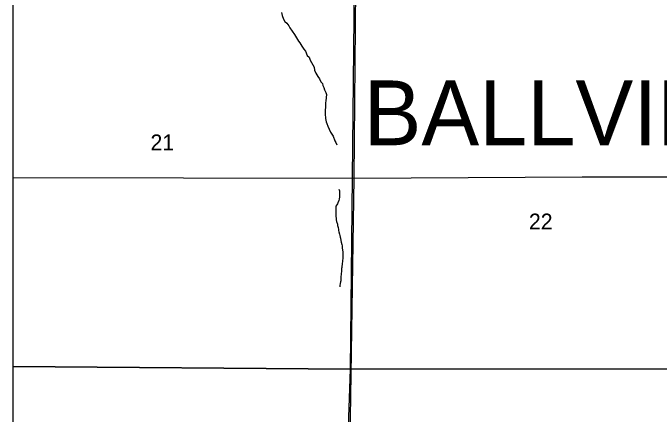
# Model space of a CAD drawing. Extents: x -8.5 to 18.7, y -20.3 to 7.
# Drawn here: x -8.459 to -5.057, y -7.025 to -4.913 of the extents above; entities that cross this region are included whole.
import ezdxf

# ---------------------------------------------------------------- set-up
doc = ezdxf.new("R2010")
doc.units = 0
for name, color, linetype in [('Default', 7, 'Continuous'), ('GM_X_Corporation', 7, 'Continuous'), ('GM_X_County_Road', 7, 'Continuous'), ('GM_X_Minor_River', 7, 'Continuous'), ('GM_X_Section', 7, 'Continuous'), ('GM_X_Section_Text', 7, 'Continuous'), ('GM_X_Township_Text', 7, 'Continuous'), ('SH_Cut_Line', 7, 'Continuous')]:
    doc.layers.add(name, color=color, linetype=linetype)

msp = doc.modelspace()

# ---------------------------------------------------------------- linework, layer by layer
at = {"layer": 'Default'}
for points in [[(-8.4587, -4.7633), (-8.4587, -6.7745), (-6.6812, -6.7894), (-6.6598, -4.7688)], [(-8.4587, -6.7745), (-8.4587, -8.687), (-6.7452, -8.6232), (-6.7444, -8.6126), (-6.6812, -6.7894)]]:
    msp.add_lwpolyline(points, close=True, dxfattribs=at)
at = {"layer": 'GM_X_Corporation'}
msp.add_lwpolyline([(-8.4587, 1.1732), (-8.4587, -10.6981)], dxfattribs=at)
at = {"layer": 'GM_X_County_Road'}
msp.add_line((-8.4587, -5.7791), (-6.6624, -5.7822), dxfattribs=at)
for points in [[(-6.6624, -5.7822), (-6.6535, -4.7817), (-6.634, -2.8913)], [(-6.8604, -10.6554), (-6.8095, -9.6404), (-6.7791, -9.1887), (-6.7402, -8.6177), (-6.6826, -7.1587), (-6.6624, -5.7822)], [(-6.6624, -5.7822), (-5.462, -5.7761), (-4.7817, -5.7756), (-4.6868, -5.7764), (-4.4626, -5.7723)]]:
    msp.add_lwpolyline(points, dxfattribs=at)
at = {"layer": 'GM_X_Minor_River'}
for points in [[(-7.044, -4.9105), (-7.0419, -4.9264), (-7.0345, -4.9462), (-7.0278, -4.9585), (-7.0172, -4.9677), (-7.0067, -4.9807), (-7.0015, -4.9906), (-6.9888, -5.0089), (-6.9768, -5.0258), (-6.9648, -5.0449), (-6.9544, -5.0609), (-6.9476, -5.0709), (-6.9379, -5.0884), (-6.9275, -5.1045), (-6.9185, -5.1144), (-6.9103, -5.1365), (-6.899, -5.1465), (-6.8931, -5.1625), (-6.8804, -5.1862), (-6.873, -5.1992), (-6.8708, -5.2136), (-6.8642, -5.2304), (-6.8537, -5.2472), (-6.844, -5.2602), (-6.838, -5.2754), (-6.8283, -5.2854), (-6.8261, -5.2953), (-6.8224, -5.306), (-6.818, -5.3181), (-6.8113, -5.3319), (-6.8083, -5.3433), (-6.8109, -5.3752), (-6.8126, -5.3865), (-6.8135, -5.4048), (-6.8153, -5.429), (-6.8154, -5.445), (-6.8126, -5.4685), (-6.8098, -5.486), (-6.8061, -5.4959), (-6.8009, -5.5097), (-6.7942, -5.5249), (-6.7868, -5.5402), (-6.7793, -5.5509), (-6.7733, -5.5616), (-6.7637, -5.586), (-6.7585, -5.5959), (-6.7525, -5.6073)], [(-6.7434, -5.8413), (-6.7397, -5.8504), (-6.739, -5.8558), (-6.7384, -5.8649), (-6.7392, -5.8755), (-6.74, -5.8808), (-6.7417, -5.8929), (-6.7433, -5.9005), (-6.7479, -5.9126), (-6.7503, -5.9179), (-6.7534, -5.9232), (-6.758, -5.9307), (-6.7588, -5.9368), (-6.759, -5.9573), (-6.7584, -5.9702), (-6.7577, -5.9786), (-6.7578, -5.9839), (-6.7571, -5.9938), (-6.7564, -6.0029), (-6.7542, -6.0105), (-6.7506, -6.025), (-6.7491, -6.0318), (-6.747, -6.0432), (-6.744, -6.0524), (-6.7441, -6.0584), (-6.7419, -6.0653), (-6.7397, -6.0775), (-6.7375, -6.0843), (-6.7353, -6.0935), (-6.7338, -6.0995), (-6.7317, -6.111), (-6.731, -6.1193), (-6.7273, -6.133), (-6.7259, -6.1399), (-6.7245, -6.1498), (-6.7238, -6.1619), (-6.7224, -6.171), (-6.7218, -6.1862), (-6.722, -6.206), (-6.7229, -6.2166), (-6.7237, -6.2227), (-6.7245, -6.231), (-6.7253, -6.2371), (-6.7269, -6.2462), (-6.7278, -6.253), (-6.7286, -6.2583), (-6.7286, -6.2636), (-6.7295, -6.2697), (-6.7295, -6.2765), (-6.7303, -6.2826), (-6.7304, -6.2902), (-6.732, -6.3008), (-6.7321, -6.3061), (-6.733, -6.316), (-6.733, -6.3236), (-6.7338, -6.3289), (-6.7355, -6.338), (-6.7371, -6.3486), (-6.7371, -6.3554)]]:
    msp.add_lwpolyline(points, dxfattribs=at)
at = {"layer": 'GM_X_Section'}
for points in [[(-4.6646, -4.7603), (-4.6877, -6.787), (-6.6812, -6.7894), (-6.6598, -4.7688)], [(-6.6812, -6.7894), (-4.6877, -6.787), (-4.6907, -7.1341), (-4.7642, -7.6263), (-4.7984, -8.6266), (-6.7444, -8.6126)]]:
    msp.add_lwpolyline(points, close=True, dxfattribs=at)
at = {"layer": 'SH_Cut_Line'}
msp.add_lwpolyline([(-8.4587, 6.938), (-8.4587, -10.6981)], dxfattribs=at)

# ---------------------------------------------------------------- texts
at = {"layer": 'GM_X_Section_Text'}
for s, p in [('21', (-7.7343, -5.6366)), ('22', (-5.7418, -6.0532))]:
    msp.add_text(s, height=0.08371, rotation=0, dxfattribs=at).set_placement(p)
at = {"layer": 'GM_X_Township_Text'}
msp.add_text('BALLVILLE', height=0.34091, rotation=0, dxfattribs=at).set_placement((-6.612, -5.6095))

doc.saveas('drawing.dxf')
